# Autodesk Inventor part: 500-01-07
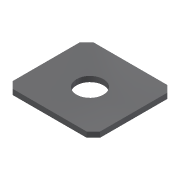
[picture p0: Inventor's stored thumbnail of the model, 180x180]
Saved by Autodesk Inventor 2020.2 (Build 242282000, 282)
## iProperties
Created: 2015-10
Part Number: 500-01-07
Material: Stal
Document SubType Name: Modeling
Designer: F.Stasiak
Density: 7.85 g/cm^3
Appearance: Płyta
Description: Ucho
Manager: www.cadconsulting.pl
Company: Fabian Stasiak CAD Consulting
Author: F.Stasiak
Subject: Zbiór ćwiczeń. Autodesk Inventor 2020. Kurs podstawowy
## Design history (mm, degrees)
sketch "Szkic1"
  geometry: L1 (65, 60)-(-65, 60); L2 (-65, 60)-(-65, -60); L3 (-65, -60)-(65, -60); L4 (65, -60)-(65, 60); L5 (65, 60)-(-65, -60); L6 (-65, 60)-(65, -60); C1 r 20 at (0, 0); 1 further point
  constraints: 12 end point, 2 midpoint, 2 parallel, 1 centre point, 1 coincident, 1 horizontal, 1 perpendicular
  dimensions: "d14" = 130 distance of L3.end L2.end; "d15" = 120 distance of L2.end L1.end; "d16" = 40 diameter of C1
extrude "Wyciągnięcie proste1" new body sketch "Szkic1" distance "d3" = 8; taper "d4" = 0 deg
chamfer "Faza1" distance "d7" = 10; stored, may be unused: second distance "d8" = 2, angle "d9" = 45 deg
node "Bryła1"
